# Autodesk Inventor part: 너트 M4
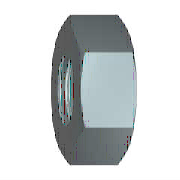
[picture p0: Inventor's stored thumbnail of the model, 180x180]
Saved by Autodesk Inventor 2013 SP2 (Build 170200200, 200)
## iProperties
IsCustomPart: 0
Created: 2012-02
Part Number: 너트 M4
Material: 스테인리스강
Description: 6각 너트, 스타일 1 - 제품 등급 A 및 B
Document SubType Name: Modeling
Standard: ISO 4032
Designer: mduedu
Standard Revision: Third edition 1999-08-15
Standards Organization: ISO
Language: ko-KR
Size Designation: M4
Categories: <MemberInstance><Categories><Category DisplayName="조임쇠" InternalName="e4da775c-781d-43d5-af7c-5136215cf5a6" Mnemonic="FSTN"><Category DisplayName="너트" InternalN
Density: 8.08 g/cm^3
Mass: 0.820715 g
Surface Area: 1.59496 cm^2
Volume: 0.101574 cm^3
Author: mduedu
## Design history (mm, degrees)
sketch "스케치1"
  geometry: L1 (-4.041, 0)-(-2.021, 3.5); L2 (-2.021, 3.5)-(2.021, 3.5); L3 (2.021, 3.5)-(4.041, 0); L4 (4.041, 0)-(2.021, -3.5); L5 (2.021, -3.5)-(-2.021, -3.5); L6 (-2.021, -3.5)-(-4.041, 0); 2 further points
  constraints: 12 end point, 1 coincident, 1 horizontal, 11 other
  dimensions: "d0" = 8.0829 distance of L3.end L1.start (= 1.1547 x SW)
extrude "본체" new body sketch "스케치1" distance "d1" = 3.2 (= KOH); taper "d2" = 0 deg
sketch "스케치2"
  geometry: L1 (0, 2.021)-(0, 4.041) reference; L2 (0, 4.041)-(3.2, 4.041) reference; L3 (3.2, 2.021)-(3.2, 4.041) reference; L4 (-0.64, 0)-(3.84, 0) reference; L5 (0.63, 4.041)-(0, 2.95); L6 (2.57, 4.041)-(3.2, 2.95)
  constraints: 4 end point, 4 point on line
  dimensions: "d3" = 30 deg angle of L1 L5 (= ANG1); "d4" = 30 deg angle of L3 L6 (= ANG2); "d5" = 5.9 diameter of L5.end L4 (= SW0); "d6" = 5.9 diameter of L6.end L4 (= SW01)
revolve "모따기1" sketch "스케치2" stored, may be unused: angle "d7" = 90 deg
sketch "스케치3"
  geometry: 4 further points
  constraints: 1 coincident, 1 other
hole "스레드" sketch "스케치3" at (0, 0) diameter "d25" = 3.242; stored, may be unused: countersink angle "d29" = 82 deg, drill point angle "d31" = 118 deg; dims "d26" = 6, "d27" = 4, "d28" = 2, "d30" = 8
workaxis "Work Axis1"
workplane "Work Plane1"
body "Solid1"
chamfer "모따기2" distance "d8" = 0.37889 (= -0.5 x GD1 + 0.5 x NND); stored, may be unused: angle "d9" = 30 deg, second distance "d40" = 0.37889 (= -0.5 x GD1 + 0.5 x NND)
chamfer "모따기3" distance "d10" = 0.37889 (= -0.5 x GD1 + 0.5 x NND); stored, may be unused: angle "d11" = 30 deg, second distance "d41" = 0.37889 (= -0.5 x GD1 + 0.5 x NND)
other parameters: "ANG1" = 30 deg [user parameter; used in 1 equation term], "ANG2" = 30 deg [user parameter; used in 1 equation term], "NND" = 4 [user parameter; used in 4 equation terms], "KOH" = 3.2 [user parameter; used in 1 equation term], "SW" = 7 [user parameter; used in 2 equation terms], "SW0" = 5.9 [user parameter; used in 2 equation terms], "SW01" = 5.9 (= SW0) [user parameter; used in 1 equation term], "GD1" = 3.24223 (computed from THREADDIA, PTC, TOA) [user parameter; used in 4 equation terms], "d13" = 0, "d14" = 0, "d39" = 0, "d42" = 0, "GUL" = 0.37889 (= 0.541266 x PTC) [user parameter], "TPU" = 14.28571 (computed from PTC) [user parameter], "THREADDIA" = 4 [user parameter; used in 1 equation term], "TOA" = 30 deg [user parameter; used in 1 equation term], "PTC" = 0.7 [user parameter; used in 4 equation terms], "E0" = 8.085 (= 1.155 x SW) [user parameter], "GAL" = 0.37889 (= 0.541266 x PTC) [user parameter]
